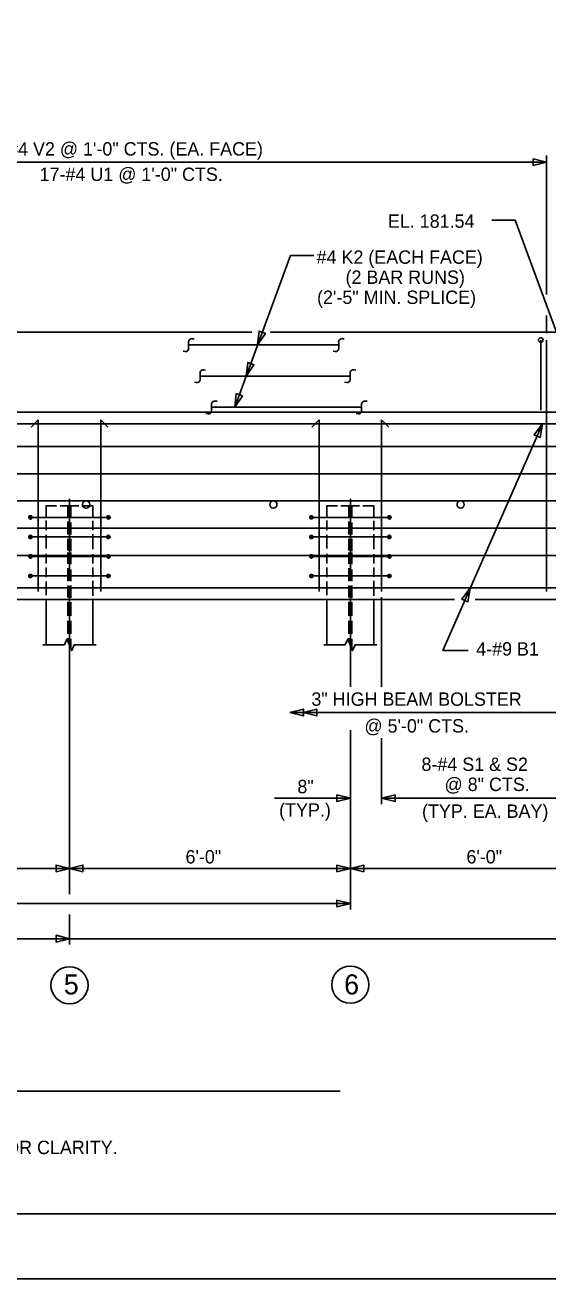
# Model space of a CAD drawing. Extents: x -41 to 191, y -168 to 6.
# Drawn here: x 38.27 to 49.44, y -50.38 to -23.59 of the extents above; entities that cross this region are included whole.
import ezdxf

# ---------------------------------------------------------------- set-up
doc = ezdxf.new("R2010")
doc.units = 0
for name, color, linetype in [('Arrowhead Terminators CELL', 7, 'Continuous'), ('Dimension Lines', 7, 'Continuous'), ('Mis Object Lines', 7, 'Continuous'), ('Mis Object Lines Hidden', 7, 'Continuous'), ('Plan Sheet CELL', 7, 'Continuous'), ('Plot Shape CELL', 7, 'Continuous'), ('Rebar Lines', 7, 'Continuous'), ('Rebar Lines CELL', 7, 'Continuous'), ('Sub End Bent Cap Lines CELL', 7, 'Continuous'), ('Text', 7, 'Continuous'), ('Title Text', 7, 'Continuous')]:
    doc.layers.add(name, color=color, linetype=linetype)

# ---------------------------------------------------------------- blocks, each defined once
blk = doc.blocks.new('AH')
at = {"layer": 'Sub End Bent Cap Lines CELL'}
blk.add_lwpolyline([(0, 0), (-1.25, 0.31), (-1.25, -0.31)], close=True, dxfattribs=at)

msp = doc.modelspace()

# ---------------------------------------------------------------- linework, layer by layer
at = {"layer": 'Arrowhead Terminators CELL'}
for p, q in [((41.763, -30.368), (41.763, -30.494)), ((41.763, -30.368), (41.763, -30.494)), ((41.882, -30.295), (41.85, -30.29)), ((41.882, -30.295), (41.85, -30.29)), ((44.969, -30.368), (44.969, -30.494)), ((44.969, -30.368), (44.969, -30.494)), ((45.087, -30.295), (45.056, -30.29)), ((45.087, -30.295), (45.056, -30.29)), ((41.685, -30.561), (41.644, -30.556)), ((41.685, -30.561), (41.644, -30.556)), ((44.891, -30.561), (44.849, -30.556)), ((44.891, -30.561), (44.849, -30.556)), ((42.008, -31.035), (42.008, -31.161)), ((42.008, -31.035), (42.008, -31.161)), ((42.126, -30.962), (42.095, -30.956)), ((42.126, -30.962), (42.095, -30.956)), ((45.214, -31.035), (45.214, -31.161)), ((45.214, -31.035), (45.214, -31.161)), ((45.332, -30.962), (45.301, -30.956)), ((45.332, -30.962), (45.301, -30.956)), ((41.93, -31.228), (41.888, -31.222)), ((41.93, -31.228), (41.888, -31.222)), ((45.136, -31.228), (45.094, -31.222)), ((45.136, -31.228), (45.094, -31.222)), ((42.253, -31.701), (42.253, -31.828)), ((42.253, -31.701), (42.253, -31.828)), ((42.371, -31.628), (42.34, -31.623)), ((42.371, -31.628), (42.34, -31.623)), ((45.459, -31.701), (45.459, -31.828)), ((45.459, -31.701), (45.459, -31.828)), ((45.577, -31.628), (45.546, -31.623)), ((45.577, -31.628), (45.546, -31.623)), ((42.175, -31.894), (42.133, -31.889)), ((42.175, -31.894), (42.133, -31.889)), ((45.38, -31.894), (45.339, -31.889)), ((45.38, -31.894), (45.339, -31.889))]:
    msp.add_line(p, q, dxfattribs=at)
for points in [[(43.238, -30.422), (43.404, -30.178), (43.27, -30.129)], [(42.993, -31.089), (43.159, -30.845), (43.025, -30.796)], [(42.748, -31.756), (42.914, -31.512), (42.78, -31.462)], [(49.324, -32.111), (49.143, -32.344), (49.274, -32.402)], [(47.78, -35.62), (47.599, -35.853), (47.73, -35.911)], [(43.925, -38.277), (44.214, -38.349), (44.214, -38.204)], [(44.214, -38.277), (44.502, -38.349), (44.502, -38.204)], [(45.219, -40.11), (44.933, -40.181), (44.933, -40.038)], [(45.886, -40.11), (46.172, -40.038), (46.172, -40.181)], [(39.219, -41.61), (38.933, -41.681), (38.933, -41.538)], [(39.219, -41.61), (39.505, -41.538), (39.505, -41.681)], [(45.219, -41.61), (44.933, -41.681), (44.933, -41.538)], [(45.219, -41.61), (45.505, -41.538), (45.505, -41.681)], [(45.219, -42.36), (44.933, -42.288), (44.933, -42.431)], [(39.219, -43.11), (38.933, -43.038), (38.933, -43.181)]]:
    msp.add_lwpolyline(points, close=True, dxfattribs=at)
for centre, radius, start, end in [((41.701, -30.499), 0.0632, 255.8326, 4.1182), ((41.701, -30.499), 0.0632, 255.8326, 4.1182), ((41.834, -30.36), 0.0712, 76.7642, 186.563), ((41.834, -30.36), 0.0712, 76.7642, 186.563), ((44.906, -30.499), 0.0632, 255.8326, 4.1182), ((44.906, -30.499), 0.0632, 255.8326, 4.1182), ((45.039, -30.36), 0.0712, 76.7642, 186.563), ((45.039, -30.36), 0.0712, 76.7642, 186.563), ((42.079, -31.026), 0.0712, 76.7642, 186.563), ((42.079, -31.026), 0.0712, 76.7642, 186.563), ((45.284, -31.026), 0.0712, 76.7642, 186.563), ((45.284, -31.026), 0.0712, 76.7642, 186.563), ((41.946, -31.166), 0.0632, 255.8326, 4.1182), ((41.946, -31.166), 0.0632, 255.8326, 4.1182), ((45.151, -31.166), 0.0632, 255.8326, 4.1182), ((45.151, -31.166), 0.0632, 255.8326, 4.1182), ((42.191, -31.833), 0.0632, 255.8326, 4.1182), ((42.191, -31.833), 0.0632, 255.8326, 4.1182), ((42.324, -31.693), 0.0712, 76.7642, 186.563), ((42.324, -31.693), 0.0712, 76.7642, 186.563), ((45.396, -31.833), 0.0632, 255.8326, 4.1182), ((45.396, -31.833), 0.0632, 255.8326, 4.1182), ((45.529, -31.693), 0.0712, 76.7642, 186.563), ((45.529, -31.693), 0.0712, 76.7642, 186.563)]:
    msp.add_arc(centre, radius, start, end, dxfattribs=at)
at = {"layer": 'Dimension Lines'}
for p, q in [((33.337, -26.52), (49.41, -26.52)), ((49.41, -29.346), (49.41, -26.377)), ((49.41, -30.175), (49.41, -29.796)), ((39.219, -35.86), (39.219, -42.157)), ((45.219, -35.86), (45.219, -37.031)), ((45.886, -35.81), (45.886, -37.728)), ((45.219, -37.136), (45.219, -37.728)), ((49.839, -38.277), (43.925, -38.277)), ((45.219, -38.653), (45.219, -42.485)), ((45.886, -38.829), (45.886, -40.235)), ((45.219, -40.11), (43.597, -40.11)), ((50.552, -40.11), (45.886, -40.11)), ((39.219, -41.61), (33.219, -41.61)), ((45.219, -41.61), (39.219, -41.61)), ((51.219, -41.61), (45.219, -41.61)), ((45.219, -42.36), (21.219, -42.36)), ((39.219, -42.592), (39.219, -43.235)), ((39.219, -43.11), (33.219, -43.11)), ((45.219, -43.11), (39.219, -43.11)), ((51.219, -43.11), (45.219, -43.11)), ((44.998, -46.37), (20.296, -46.37))]:
    msp.add_line(p, q, dxfattribs=at)
for points in [[(49.619, -30.152), (48.738, -27.754), (48.238, -27.754)], [(42.748, -31.756), (43.941, -28.51), (44.441, -28.51)], [(49.324, -32.111), (47.194, -36.952), (47.735, -36.952)]]:
    msp.add_lwpolyline(points, dxfattribs=at)
for centre in [(39.219, -44.105), (45.219, -44.093)]:
    msp.add_circle(centre, 0.397, dxfattribs=at)
at = {"layer": 'Mis Object Lines'}
for p, q in [((43.116, -30.152), (16.026, -30.152)), ((49.619, -30.152), (43.512, -30.152)), ((47.445, -35.86), (12.601, -35.86)), ((53.837, -35.86), (47.886, -35.86))]:
    msp.add_line(p, q, dxfattribs=at)
at = {"layer": 'Mis Object Lines Hidden'}
msp.add_line((49.619, -31.86), (12.601, -31.86), dxfattribs=at)
at = {"layer": 'Plan Sheet CELL'}
msp.add_line((2.414, -48.992), (75.694, -48.992), dxfattribs=at)
at = {"layer": 'Plot Shape CELL'}
msp.add_lwpolyline([(0, 0), (75.715, 0), (75.715, -50.38), (0, -50.38)], close=True, dxfattribs=at)
at = {"layer": 'Rebar Lines'}
for p, q in [((41.762, -30.422), (44.967, -30.422)), ((49.285, -31.818), (49.285, -30.318)), ((49.41, -35.693), (49.41, -30.318)), ((42.007, -31.089), (45.212, -31.089)), ((42.252, -31.756), (45.457, -31.756)), ((53.096, -32.111), (14.053, -32.111)), ((38.552, -32.027), (38.399, -32.18)), ((38.552, -35.693), (38.552, -32.027)), ((39.886, -35.693), (39.886, -32.027)), ((39.886, -32.027), (40.039, -32.18)), ((44.552, -32.027), (44.399, -32.18)), ((44.552, -35.693), (44.552, -32.027)), ((45.886, -35.693), (45.886, -32.027)), ((45.886, -32.027), (46.039, -32.18)), ((53.554, -32.591), (31.629, -32.591)), ((53.554, -33.174), (31.629, -33.174)), ((39.219, -33.709), (39.219, -35.465)), ((45.219, -33.709), (45.219, -35.465)), ((53.554, -33.757), (31.629, -33.757)), ((39.187, -34.103), (39.187, -33.86)), ((39.25, -34.108), (39.25, -33.86)), ((45.187, -34.103), (45.187, -33.86)), ((45.25, -34.108), (45.25, -33.86)), ((39.187, -34.474), (39.187, -34.196)), ((39.25, -34.474), (39.25, -34.219)), ((45.187, -34.474), (45.187, -34.196)), ((45.25, -34.474), (45.25, -34.219)), ((53.554, -34.34), (31.629, -34.34)), ((39.187, -34.817), (39.187, -34.567)), ((39.25, -34.829), (39.25, -34.567)), ((45.187, -34.817), (45.187, -34.567)), ((45.25, -34.829), (45.25, -34.567)), ((53.554, -34.924), (31.629, -34.924)), ((39.187, -35.103), (39.187, -34.86)), ((39.25, -35.108), (39.25, -34.86)), ((45.187, -35.103), (45.187, -34.86)), ((45.25, -35.108), (45.25, -34.86)), ((39.187, -35.474), (39.187, -35.196)), ((39.25, -35.474), (39.25, -35.219)), ((45.187, -35.474), (45.187, -35.196)), ((45.25, -35.474), (45.25, -35.219)), ((53.096, -35.61), (13.96, -35.61)), ((39.187, -35.817), (39.187, -35.567)), ((39.219, -35.57), (39.219, -35.86)), ((39.25, -35.829), (39.25, -35.567)), ((45.187, -35.817), (45.187, -35.567)), ((45.219, -35.57), (45.219, -35.86)), ((45.25, -35.829), (45.25, -35.567)), ((38.718, -35.877), (38.718, -36.829)), ((39.72, -35.877), (39.72, -36.829)), ((44.718, -35.877), (44.718, -36.829)), ((45.72, -35.877), (45.72, -36.829)), ((39.187, -36.212), (39.187, -35.916)), ((39.219, -35.93), (39.219, -37.136)), ((39.25, -36.212), (39.25, -35.922)), ((45.187, -36.212), (45.187, -35.916)), ((45.219, -35.93), (45.219, -37.136)), ((45.25, -36.212), (45.25, -35.922)), ((39.187, -36.595), (39.187, -36.322)), ((39.25, -36.595), (39.25, -36.317)), ((45.187, -36.595), (45.187, -36.322)), ((45.25, -36.595), (45.25, -36.317)), ((39.187, -36.763), (39.187, -36.689)), ((39.25, -36.913), (39.25, -36.7)), ((45.187, -36.763), (45.187, -36.689)), ((45.25, -36.913), (45.25, -36.7))]:
    msp.add_line(p, q, dxfattribs=at)
for points in [[(38.718, -34.094), (38.718, -33.86), (38.941, -33.86)], [(39.017, -33.86), (39.416, -33.86)], [(39.486, -33.86), (39.718, -33.86), (39.718, -34.106)], [(44.718, -34.094), (44.718, -33.86), (44.941, -33.86)], [(45.017, -33.86), (45.416, -33.86)], [(45.486, -33.86), (45.718, -33.86), (45.718, -34.106)], [(38.718, -34.384), (38.718, -34.176)], [(39.718, -34.182), (39.718, -34.381)], [(44.718, -34.384), (44.718, -34.176)], [(45.718, -34.182), (45.718, -34.381)], [(38.718, -34.771), (38.718, -34.48)], [(39.718, -34.467), (39.718, -34.787)], [(44.718, -34.771), (44.718, -34.48)], [(45.718, -34.467), (45.718, -34.787)], [(38.718, -35.094), (38.718, -34.886)], [(39.718, -34.892), (39.718, -35.091)], [(44.718, -35.094), (44.718, -34.886)], [(45.718, -34.892), (45.718, -35.091)], [(38.718, -35.384), (38.718, -35.176)], [(39.718, -35.182), (39.718, -35.381)], [(44.718, -35.384), (44.718, -35.176)], [(45.718, -35.182), (45.718, -35.381)], [(38.718, -35.771), (38.718, -35.48)], [(39.718, -35.467), (39.718, -35.787)], [(44.718, -35.771), (44.718, -35.48)], [(45.718, -35.467), (45.718, -35.787)], [(38.649, -36.829), (39.111, -36.829), (39.165, -36.71), (39.267, -36.954), (39.319, -36.829), (39.786, -36.829)], [(44.649, -36.829), (45.111, -36.829), (45.165, -36.71), (45.267, -36.954), (45.319, -36.829), (45.786, -36.829)]]:
    msp.add_lwpolyline(points, dxfattribs=at)
msp.add_circle((49.285, -30.318), 0.0495, dxfattribs=at)
at = {"layer": 'Rebar Lines CELL'}
for p, q in [((40.052, -34.11), (38.386, -34.11)), ((46.052, -34.11), (44.386, -34.11)), ((40.052, -34.527), (38.386, -34.527)), ((46.052, -34.527), (44.386, -34.527)), ((40.052, -34.943), (38.386, -34.943)), ((46.052, -34.943), (44.386, -34.943)), ((40.052, -35.36), (38.386, -35.36)), ((46.052, -35.36), (44.386, -35.36))]:
    msp.add_line(p, q, dxfattribs=at)
for points in [[(38.386, -34.075), (38.372, -34.077), (38.361, -34.085), (38.353, -34.096), (38.35, -34.11), (38.353, -34.123), (38.361, -34.135), (38.372, -34.142), (38.386, -34.145), (38.399, -34.142), (38.41, -34.135), (38.418, -34.123), (38.421, -34.11), (38.418, -34.096), (38.411, -34.085), (38.399, -34.077), (38.386, -34.075), (38.386, -34.11), (38.386, -34.145), (38.372, -34.142), (38.386, -34.11), (38.361, -34.135), (38.353, -34.123), (38.386, -34.11), (38.35, -34.11), (38.353, -34.096), (38.386, -34.11), (38.361, -34.085), (38.372, -34.077), (38.386, -34.11), (38.399, -34.077), (38.411, -34.085), (38.386, -34.11), (38.418, -34.096), (38.421, -34.11), (38.386, -34.11), (38.418, -34.123), (38.41, -34.135), (38.386, -34.11), (38.399, -34.142)], [(40.052, -34.075), (40.039, -34.077), (40.027, -34.085), (40.02, -34.096), (40.017, -34.11), (40.02, -34.123), (40.027, -34.135), (40.039, -34.142), (40.052, -34.145), (40.066, -34.142), (40.077, -34.135), (40.085, -34.123), (40.088, -34.11), (40.085, -34.096), (40.077, -34.085), (40.066, -34.077), (40.052, -34.075), (40.052, -34.11), (40.052, -34.145), (40.039, -34.142), (40.052, -34.11), (40.027, -34.135), (40.02, -34.123), (40.052, -34.11), (40.017, -34.11), (40.02, -34.096), (40.052, -34.11), (40.027, -34.085), (40.039, -34.077), (40.052, -34.11), (40.066, -34.077), (40.077, -34.085), (40.052, -34.11), (40.085, -34.096), (40.088, -34.11), (40.052, -34.11), (40.085, -34.123), (40.077, -34.135), (40.052, -34.11), (40.066, -34.142)], [(44.386, -34.075), (44.372, -34.077), (44.361, -34.085), (44.353, -34.096), (44.35, -34.11), (44.353, -34.123), (44.361, -34.135), (44.372, -34.142), (44.386, -34.145), (44.399, -34.142), (44.41, -34.135), (44.418, -34.123), (44.421, -34.11), (44.418, -34.096), (44.411, -34.085), (44.399, -34.077), (44.386, -34.075), (44.386, -34.11), (44.386, -34.145), (44.372, -34.142), (44.386, -34.11), (44.361, -34.135), (44.353, -34.123), (44.386, -34.11), (44.35, -34.11), (44.353, -34.096), (44.386, -34.11), (44.361, -34.085), (44.372, -34.077), (44.386, -34.11), (44.399, -34.077), (44.411, -34.085), (44.386, -34.11), (44.418, -34.096), (44.421, -34.11), (44.386, -34.11), (44.418, -34.123), (44.41, -34.135), (44.386, -34.11), (44.399, -34.142)], [(46.052, -34.075), (46.039, -34.077), (46.027, -34.085), (46.02, -34.096), (46.017, -34.11), (46.02, -34.123), (46.027, -34.135), (46.039, -34.142), (46.052, -34.145), (46.066, -34.142), (46.077, -34.135), (46.085, -34.123), (46.088, -34.11), (46.085, -34.096), (46.077, -34.085), (46.066, -34.077), (46.052, -34.075), (46.052, -34.11), (46.052, -34.145), (46.039, -34.142), (46.052, -34.11), (46.027, -34.135), (46.02, -34.123), (46.052, -34.11), (46.017, -34.11), (46.02, -34.096), (46.052, -34.11), (46.027, -34.085), (46.039, -34.077), (46.052, -34.11), (46.066, -34.077), (46.077, -34.085), (46.052, -34.11), (46.085, -34.096), (46.088, -34.11), (46.052, -34.11), (46.085, -34.123), (46.077, -34.135), (46.052, -34.11), (46.066, -34.142)], [(38.386, -34.491), (38.372, -34.494), (38.361, -34.502), (38.353, -34.513), (38.35, -34.527), (38.353, -34.54), (38.361, -34.551), (38.372, -34.559), (38.386, -34.562), (38.399, -34.559), (38.41, -34.551), (38.418, -34.54), (38.421, -34.527), (38.418, -34.513), (38.411, -34.502), (38.399, -34.494), (38.386, -34.491), (38.386, -34.527), (38.386, -34.562), (38.372, -34.559), (38.386, -34.527), (38.361, -34.551), (38.353, -34.54), (38.386, -34.527), (38.35, -34.527), (38.353, -34.513), (38.386, -34.527), (38.361, -34.502), (38.372, -34.494), (38.386, -34.527), (38.399, -34.494), (38.411, -34.502), (38.386, -34.527), (38.418, -34.513), (38.421, -34.527), (38.386, -34.527), (38.418, -34.54), (38.41, -34.551), (38.386, -34.527), (38.399, -34.559)], [(40.052, -34.491), (40.039, -34.494), (40.027, -34.502), (40.02, -34.513), (40.017, -34.527), (40.02, -34.54), (40.027, -34.551), (40.039, -34.559), (40.052, -34.562), (40.066, -34.559), (40.077, -34.551), (40.085, -34.54), (40.088, -34.527), (40.085, -34.513), (40.077, -34.502), (40.066, -34.494), (40.052, -34.491), (40.052, -34.527), (40.052, -34.562), (40.039, -34.559), (40.052, -34.527), (40.027, -34.551), (40.02, -34.54), (40.052, -34.527), (40.017, -34.527), (40.02, -34.513), (40.052, -34.527), (40.027, -34.502), (40.039, -34.494), (40.052, -34.527), (40.066, -34.494), (40.077, -34.502), (40.052, -34.527), (40.085, -34.513), (40.088, -34.527), (40.052, -34.527), (40.085, -34.54), (40.077, -34.551), (40.052, -34.527), (40.066, -34.559)], [(44.386, -34.491), (44.372, -34.494), (44.361, -34.502), (44.353, -34.513), (44.35, -34.527), (44.353, -34.54), (44.361, -34.551), (44.372, -34.559), (44.386, -34.562), (44.399, -34.559), (44.41, -34.551), (44.418, -34.54), (44.421, -34.527), (44.418, -34.513), (44.411, -34.502), (44.399, -34.494), (44.386, -34.491), (44.386, -34.527), (44.386, -34.562), (44.372, -34.559), (44.386, -34.527), (44.361, -34.551), (44.353, -34.54), (44.386, -34.527), (44.35, -34.527), (44.353, -34.513), (44.386, -34.527), (44.361, -34.502), (44.372, -34.494), (44.386, -34.527), (44.399, -34.494), (44.411, -34.502), (44.386, -34.527), (44.418, -34.513), (44.421, -34.527), (44.386, -34.527), (44.418, -34.54), (44.41, -34.551), (44.386, -34.527), (44.399, -34.559)], [(46.052, -34.491), (46.039, -34.494), (46.027, -34.502), (46.02, -34.513), (46.017, -34.527), (46.02, -34.54), (46.027, -34.551), (46.039, -34.559), (46.052, -34.562), (46.066, -34.559), (46.077, -34.551), (46.085, -34.54), (46.088, -34.527), (46.085, -34.513), (46.077, -34.502), (46.066, -34.494), (46.052, -34.491), (46.052, -34.527), (46.052, -34.562), (46.039, -34.559), (46.052, -34.527), (46.027, -34.551), (46.02, -34.54), (46.052, -34.527), (46.017, -34.527), (46.02, -34.513), (46.052, -34.527), (46.027, -34.502), (46.039, -34.494), (46.052, -34.527), (46.066, -34.494), (46.077, -34.502), (46.052, -34.527), (46.085, -34.513), (46.088, -34.527), (46.052, -34.527), (46.085, -34.54), (46.077, -34.551), (46.052, -34.527), (46.066, -34.559)], [(38.386, -34.908), (38.372, -34.911), (38.361, -34.918), (38.353, -34.93), (38.35, -34.943), (38.353, -34.957), (38.361, -34.968), (38.372, -34.976), (38.386, -34.978), (38.399, -34.976), (38.41, -34.968), (38.418, -34.957), (38.421, -34.943), (38.418, -34.93), (38.411, -34.918), (38.399, -34.911), (38.386, -34.908), (38.386, -34.943), (38.386, -34.978), (38.372, -34.976), (38.386, -34.943), (38.361, -34.968), (38.353, -34.957), (38.386, -34.943), (38.35, -34.943), (38.353, -34.93), (38.386, -34.943), (38.361, -34.918), (38.372, -34.911), (38.386, -34.943), (38.399, -34.911), (38.411, -34.918), (38.386, -34.943), (38.418, -34.93), (38.421, -34.943), (38.386, -34.943), (38.418, -34.957), (38.41, -34.968), (38.386, -34.943), (38.399, -34.976)], [(40.052, -34.908), (40.039, -34.911), (40.027, -34.918), (40.02, -34.93), (40.017, -34.943), (40.02, -34.957), (40.027, -34.968), (40.039, -34.976), (40.052, -34.978), (40.066, -34.976), (40.077, -34.968), (40.085, -34.957), (40.088, -34.943), (40.085, -34.93), (40.077, -34.918), (40.066, -34.911), (40.052, -34.908), (40.052, -34.943), (40.052, -34.978), (40.039, -34.976), (40.052, -34.943), (40.027, -34.968), (40.02, -34.957), (40.052, -34.943), (40.017, -34.943), (40.02, -34.93), (40.052, -34.943), (40.027, -34.918), (40.039, -34.911), (40.052, -34.943), (40.066, -34.911), (40.077, -34.918), (40.052, -34.943), (40.085, -34.93), (40.088, -34.943), (40.052, -34.943), (40.085, -34.957), (40.077, -34.968), (40.052, -34.943), (40.066, -34.976)], [(44.386, -34.908), (44.372, -34.911), (44.361, -34.918), (44.353, -34.93), (44.35, -34.943), (44.353, -34.957), (44.361, -34.968), (44.372, -34.976), (44.386, -34.978), (44.399, -34.976), (44.41, -34.968), (44.418, -34.957), (44.421, -34.943), (44.418, -34.93), (44.411, -34.918), (44.399, -34.911), (44.386, -34.908), (44.386, -34.943), (44.386, -34.978), (44.372, -34.976), (44.386, -34.943), (44.361, -34.968), (44.353, -34.957), (44.386, -34.943), (44.35, -34.943), (44.353, -34.93), (44.386, -34.943), (44.361, -34.918), (44.372, -34.911), (44.386, -34.943), (44.399, -34.911), (44.411, -34.918), (44.386, -34.943), (44.418, -34.93), (44.421, -34.943), (44.386, -34.943), (44.418, -34.957), (44.41, -34.968), (44.386, -34.943), (44.399, -34.976)], [(46.052, -34.908), (46.039, -34.911), (46.027, -34.918), (46.02, -34.93), (46.017, -34.943), (46.02, -34.957), (46.027, -34.968), (46.039, -34.976), (46.052, -34.978), (46.066, -34.976), (46.077, -34.968), (46.085, -34.957), (46.088, -34.943), (46.085, -34.93), (46.077, -34.918), (46.066, -34.911), (46.052, -34.908), (46.052, -34.943), (46.052, -34.978), (46.039, -34.976), (46.052, -34.943), (46.027, -34.968), (46.02, -34.957), (46.052, -34.943), (46.017, -34.943), (46.02, -34.93), (46.052, -34.943), (46.027, -34.918), (46.039, -34.911), (46.052, -34.943), (46.066, -34.911), (46.077, -34.918), (46.052, -34.943), (46.085, -34.93), (46.088, -34.943), (46.052, -34.943), (46.085, -34.957), (46.077, -34.968), (46.052, -34.943), (46.066, -34.976)], [(38.386, -35.325), (38.372, -35.327), (38.361, -35.335), (38.353, -35.346), (38.35, -35.36), (38.353, -35.373), (38.361, -35.385), (38.372, -35.392), (38.386, -35.395), (38.399, -35.392), (38.41, -35.385), (38.418, -35.373), (38.421, -35.36), (38.418, -35.346), (38.411, -35.335), (38.399, -35.327), (38.386, -35.325), (38.386, -35.36), (38.386, -35.395), (38.372, -35.392), (38.386, -35.36), (38.361, -35.385), (38.353, -35.373), (38.386, -35.36), (38.35, -35.36), (38.353, -35.346), (38.386, -35.36), (38.361, -35.335), (38.372, -35.327), (38.386, -35.36), (38.399, -35.327), (38.411, -35.335), (38.386, -35.36), (38.418, -35.346), (38.421, -35.36), (38.386, -35.36), (38.418, -35.373), (38.41, -35.385), (38.386, -35.36), (38.399, -35.392)], [(40.052, -35.325), (40.039, -35.327), (40.027, -35.335), (40.02, -35.346), (40.017, -35.36), (40.02, -35.373), (40.027, -35.385), (40.039, -35.392), (40.052, -35.395), (40.066, -35.392), (40.077, -35.385), (40.085, -35.373), (40.088, -35.36), (40.085, -35.346), (40.077, -35.335), (40.066, -35.327), (40.052, -35.325), (40.052, -35.36), (40.052, -35.395), (40.039, -35.392), (40.052, -35.36), (40.027, -35.385), (40.02, -35.373), (40.052, -35.36), (40.017, -35.36), (40.02, -35.346), (40.052, -35.36), (40.027, -35.335), (40.039, -35.327), (40.052, -35.36), (40.066, -35.327), (40.077, -35.335), (40.052, -35.36), (40.085, -35.346), (40.088, -35.36), (40.052, -35.36), (40.085, -35.373), (40.077, -35.385), (40.052, -35.36), (40.066, -35.392)], [(44.386, -35.325), (44.372, -35.327), (44.361, -35.335), (44.353, -35.346), (44.35, -35.36), (44.353, -35.373), (44.361, -35.385), (44.372, -35.392), (44.386, -35.395), (44.399, -35.392), (44.41, -35.385), (44.418, -35.373), (44.421, -35.36), (44.418, -35.346), (44.411, -35.335), (44.399, -35.327), (44.386, -35.325), (44.386, -35.36), (44.386, -35.395), (44.372, -35.392), (44.386, -35.36), (44.361, -35.385), (44.353, -35.373), (44.386, -35.36), (44.35, -35.36), (44.353, -35.346), (44.386, -35.36), (44.361, -35.335), (44.372, -35.327), (44.386, -35.36), (44.399, -35.327), (44.411, -35.335), (44.386, -35.36), (44.418, -35.346), (44.421, -35.36), (44.386, -35.36), (44.418, -35.373), (44.41, -35.385), (44.386, -35.36), (44.399, -35.392)], [(46.052, -35.325), (46.039, -35.327), (46.027, -35.335), (46.02, -35.346), (46.017, -35.36), (46.02, -35.373), (46.027, -35.385), (46.039, -35.392), (46.052, -35.395), (46.066, -35.392), (46.077, -35.385), (46.085, -35.373), (46.088, -35.36), (46.085, -35.346), (46.077, -35.335), (46.066, -35.327), (46.052, -35.325), (46.052, -35.36), (46.052, -35.395), (46.039, -35.392), (46.052, -35.36), (46.027, -35.385), (46.02, -35.373), (46.052, -35.36), (46.017, -35.36), (46.02, -35.346), (46.052, -35.36), (46.027, -35.335), (46.039, -35.327), (46.052, -35.36), (46.066, -35.327), (46.077, -35.335), (46.052, -35.36), (46.085, -35.346), (46.088, -35.36), (46.052, -35.36), (46.085, -35.373), (46.077, -35.385), (46.052, -35.36), (46.066, -35.392)]]:
    msp.add_lwpolyline(points, dxfattribs=at)
for centre in [(39.574, -33.834), (43.574, -33.834), (47.574, -33.834)]:
    msp.add_circle(centre, 0.0773, dxfattribs=at)

# ---------------------------------------------------------------- block references
at = {"layer": 'Arrowhead Terminators CELL', "xscale": 0.2288, "yscale": 0.2288}
msp.add_blockref('AH', (49.41, -26.52), dxfattribs=at)

# ---------------------------------------------------------------- texts
at = {"layer": 'Text'}
for s, p in [('17-#4 V2 @ 1\'-0" CTS. (EA. FACE)', (37.355, -26.377)), ('17-#4 U1 @ 1\'-0" CTS.', (38.581, -26.92)), ('EL. 181.54', (46.02, -27.921)), ('#4 K2 (EACH FACE)', (44.497, -28.69)), ('(2 BAR RUNS)', (45.115, -29.119)), ('(2\'-5" MIN. SPLICE) ', (44.507, -29.548)), ('4-#9 B1', (47.906, -37.061)), ('3" HIGH BEAM BOLSTER', (44.386, -38.134)), ('@ 5\'-0" CTS.', (45.519, -38.706)), ('8-#4 S1 & S2', (46.737, -39.526)), ('8"', (44.087, -40.003)), ('@ 8" CTS.', (47.23, -39.955)), ('(TYP.)', (43.697, -40.503)), ('(TYP. EA. BAY)', (46.749, -40.528)), ('6\'-0"', (41.697, -41.503)), ('6\'-0"', (47.697, -41.503))]:
    msp.add_text(s, height=0.286, dxfattribs=at).set_placement(p)
msp.add_text('CONCRETE COLLARS FOR STEEL PILES NOT SHOWN IN PLAN AND ELEVATION VIEWS FOR CLARITY.', height=0.286, rotation=360, dxfattribs=at).set_placement((21.461, -47.713))
at = {"layer": 'Title Text'}
for s, p in [('5', (39.097, -44.301)), ('6', (45.086, -44.301))]:
    msp.add_text(s, height=0.429, dxfattribs=at).set_placement(p)

doc.saveas('drawing.dxf')
